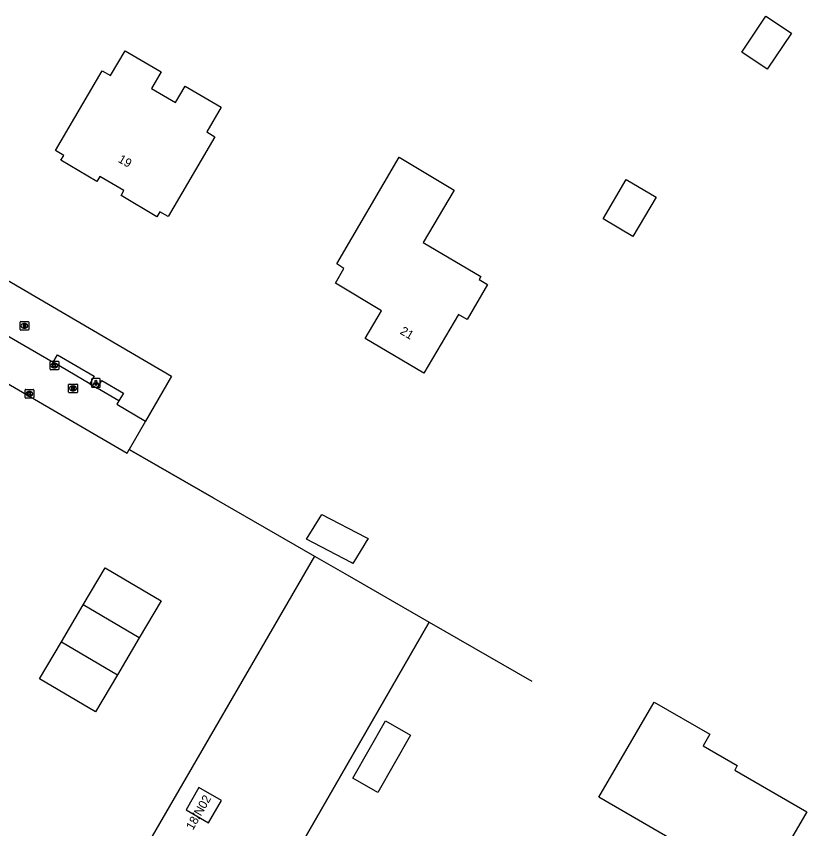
# Model space of a CAD drawing. Extents: x 156502 to 159074, y 384229 to 386094.
# Drawn here: x 157237.7 to 157328.7, y 385788.7 to 385882.2 of the extents above; entities that cross this region are included whole.
import ezdxf

# ---------------------------------------------------------------- set-up
doc = ezdxf.new("R2010")
doc.units = 0
for name, color, linetype in [('IMGEO_Gemengd_bos', 7, 'Continuous'), ('IMGEO_Grasland_overig', 7, 'Continuous'), ('IMGEO_Hek', 7, 'Continuous'), ('IMGEO_Kolk', 7, 'Continuous'), ('IMGEO_Lichtpunt', 7, 'Continuous'), ('IMGEO_Pand', 7, 'Continuous'), ('IMGEO_Pand_nummerreeks', 7, 'Continuous'), ('IMGEO_Pand_vergunning_verleend', 7, 'Continuous'), ('IMGEO_Rijbaan_lokaal_open', 7, 'Continuous'), ('IMGEO_Rioolput', 7, 'Continuous'), ('IMGEO_Voetpad_open', 7, 'Continuous')]:
    doc.layers.add(name, color=color, linetype=linetype)

msp = doc.modelspace()

# ---------------------------------------------------------------- linework, layer by layer
at = {"layer": 'IMGEO_Gemengd_bos'}
for points in [[(157272.043, 385820.045), (157246.925, 385776.791)], [(157272.043, 385820.045), (157275.516, 385818.046), (157285.222, 385812.462), (157254.627, 385759.261), (157295.91, 385735.365), (157303.574, 385730.965)]]:
    msp.add_lwpolyline(points, dxfattribs=at)
at = {"layer": 'IMGEO_Grasland_overig'}
msp.add_lwpolyline([(157250.702, 385832.309), (157260.436, 385826.723), (157272.043, 385820.045)], dxfattribs=at)
at = {"layer": 'IMGEO_Hek'}
for points in [[(157250.457, 385831.882), (157250.702, 385832.309)], [(157260.436, 385826.723), (157250.702, 385832.309)], [(157260.436, 385826.723), (157272.043, 385820.045)], [(157272.043, 385820.045), (157275.516, 385818.046)], [(157275.516, 385818.046), (157285.222, 385812.462)], [(157295.91, 385735.365), (157254.627, 385759.261), (157285.222, 385812.462)], [(157285.222, 385812.462), (157297.051, 385805.656)]]:
    msp.add_lwpolyline(points, dxfattribs=at)
at = {"layer": 'IMGEO_Kolk'}
for p, q in [((157241.584, 385841.563), (157241.584, 385842.415)), ((157241.659, 385842.489), (157242.511, 385842.489)), ((157242.095, 385841.709), (157242.07, 385841.709)), ((157242.072, 385842.269), (157242.097, 385842.269)), ((157242.585, 385842.415), (157242.585, 385841.563)), ((157242.511, 385841.489), (157241.659, 385841.489)), ((157238.706, 385838.307), (157238.706, 385839.159)), ((157238.781, 385839.233), (157239.633, 385839.233)), ((157239.194, 385839.013), (157239.219, 385839.013)), ((157239.707, 385839.159), (157239.707, 385838.307)), ((157239.633, 385838.233), (157238.781, 385838.233)), ((157239.217, 385838.453), (157239.192, 385838.453))]:
    msp.add_line(p, q, dxfattribs=at)
for points in [[(157241.584, 385841.563), (157241.584, 385842.415)], [(157241.659, 385842.489), (157242.511, 385842.489)], [(157241.905, 385842.189), (157242.028, 385842.189), (157242.028, 385842.038), (157242.158, 385842.189), (157242.322, 385842.189), (157242.176, 385842.038), (157242.329, 385841.789), (157242.177, 385841.789), (157242.092, 385841.953), (157242.028, 385841.886), (157242.028, 385841.789), (157241.905, 385841.789), (157241.905, 385842.189)], [(157242.585, 385842.415), (157242.585, 385841.563)], [(157242.511, 385841.489), (157241.659, 385841.489)], [(157238.706, 385838.307), (157238.706, 385839.159)], [(157238.781, 385839.233), (157239.633, 385839.233)], [(157239.027, 385838.933), (157239.15, 385838.933), (157239.15, 385838.782), (157239.28, 385838.933), (157239.444, 385838.933), (157239.298, 385838.782), (157239.451, 385838.533), (157239.299, 385838.533), (157239.214, 385838.697), (157239.15, 385838.63), (157239.15, 385838.533), (157239.027, 385838.533), (157239.027, 385838.933)], [(157239.707, 385839.159), (157239.707, 385838.307)], [(157239.633, 385838.233), (157238.781, 385838.233)]]:
    msp.add_lwpolyline(points, dxfattribs=at)
for centre, start, end in [((157241.661, 385842.413), 91.55205, 178.44795), ((157241.661, 385842.413), 91.55205, 178.44795), ((157242.509, 385842.413), 1.55205, 88.44795), ((157242.509, 385842.413), 1.55205, 88.44795), ((157241.661, 385841.565), 181.55205, 268.44795), ((157241.661, 385841.565), 181.55205, 268.44795), ((157242.509, 385841.565), 271.55205, 358.44795), ((157242.509, 385841.565), 271.55205, 358.44795), ((157238.783, 385839.157), 91.55205, 178.44795), ((157238.783, 385839.157), 91.55205, 178.44795), ((157239.631, 385839.157), 1.55205, 88.44795), ((157239.631, 385839.157), 1.55205, 88.44795), ((157238.783, 385838.309), 181.55205, 268.44795), ((157238.783, 385838.309), 181.55205, 268.44795), ((157239.631, 385838.309), 271.55205, 358.44795), ((157239.631, 385838.309), 271.55205, 358.44795)]:
    msp.add_arc(centre, 0.0765, start, end, dxfattribs=at)
for centre, major_axis, ratio, start_param, end_param in [((157242.071, 385841.989), (-0.387, 0.002), 0.722429, 4.712389, 7.853982), ((157242.096, 385841.989), (-0.39, 0.002), 0.717154, 1.570796, 4.712389), ((157239.193, 385838.733), (-0.387, 0.002), 0.722429, 4.712389, 7.853982), ((157239.218, 385838.733), (-0.39, 0.002), 0.717154, 1.570796, 4.712389)]:
    msp.add_ellipse(centre, major_axis=major_axis, ratio=ratio, start_param=start_param, end_param=end_param, dxfattribs=at)
at = {"layer": 'IMGEO_Lichtpunt'}
for p, q in [((157246.368, 385840.387), (157246.368, 385839.58)), ((157246.368, 385840.387), (157246.368, 385839.58)), ((157247.27, 385840.482), (157246.462, 385840.482)), ((157247.27, 385840.482), (157246.462, 385840.482)), ((157247.364, 385839.58), (157247.364, 385840.387)), ((157247.364, 385839.58), (157247.364, 385840.387)), ((157246.462, 385839.486), (157247.27, 385839.486)), ((157246.462, 385839.486), (157247.27, 385839.486))]:
    msp.add_line(p, q, dxfattribs=at)
for points in [[(157246.742, 385840.051), (157246.781, 385840.023), (157246.593, 385839.761), (157246.555, 385839.788), (157246.742, 385840.051)], [(157246.844, 385840.003), (157246.891, 385840.003), (157246.891, 385839.681), (157246.844, 385839.681), (157246.844, 385840.003)], [(157246.954, 385840.023), (157246.992, 385840.05), (157247.179, 385839.788), (157247.14, 385839.76), (157246.954, 385840.023)]]:
    msp.add_lwpolyline(points, dxfattribs=at)
msp.add_circle((157246.867, 385840.185), 0.0994, dxfattribs=at)
for centre, start, end in [((157246.462, 385840.387), 90, 180), ((157246.462, 385840.387), 90, 180), ((157247.27, 385840.387), 0, 90), ((157247.27, 385840.387), 0, 90), ((157246.462, 385839.58), 180, 270), ((157246.462, 385839.58), 180, 270), ((157247.27, 385839.58), 270, 0), ((157247.27, 385839.58), 270, 360)]:
    msp.add_arc(centre, 0.0946, start, end, dxfattribs=at)
at = {"layer": 'IMGEO_Pand'}
for points in [[(157321.246, 385878.052), (157324.014, 385882.185), (157326.945, 385880.221), (157324.176, 385876.089), (157321.246, 385878.052)], [(157242.826, 385865.609), (157243.156, 385866.162), (157242.212, 385866.726), (157247.585, 385875.898), (157248.555, 385875.375), (157250.234, 385878.2), (157254.372, 385875.786), (157253.258, 385873.877), (157256.043, 385872.253), (157257.148, 385874.146), (157261.288, 385871.729), (157259.62, 385868.87), (157260.57, 385868.316), (157255.182, 385859.122), (157254.232, 385859.683), (157253.898, 385859.114), (157249.757, 385861.548), (157250.086, 385862.113), (157247.316, 385863.723), (157246.981, 385863.155), (157242.826, 385865.609)], [(157281.782, 385865.949), (157288.102, 385862.187), (157284.558, 385856.153), (157291.197, 385852.247), (157290.981, 385851.88), (157291.963, 385851.3), (157289.6, 385847.295), (157288.628, 385847.855), (157284.619, 385841.103), (157277.855, 385845.082), (157279.744, 385848.293), (157274.438, 385851.45), (157275.432, 385853.153), (157274.591, 385853.675), (157281.782, 385865.949)], [(157307.932, 385863.396), (157311.381, 385861.357), (157308.708, 385856.835), (157305.259, 385858.875), (157307.932, 385863.396)], [(157277.909, 385822.228), (157278.209, 385822.071), (157278.002, 385821.731), (157277.726, 385821.278), (157276.462, 385819.199), (157276.241, 385819.314), (157271.119, 385821.984), (157272.866, 385824.855), (157277.909, 385822.228)], [(157317.548, 385799.558), (157316.776, 385798.21), (157320.718, 385795.937), (157320.434, 385795.406), (157328.719, 385790.614), (157326.966, 385787.584), (157327.534, 385787.243), (157326.922, 385786.2), (157328.262, 385785.426), (157325.36, 385780.382), (157319.65, 385783.69), (157315.58, 385786.049), (157304.76, 385792.318), (157311.146, 385803.25), (157317.548, 385799.558)], [(157280.225, 385801.102), (157283.103, 385799.455), (157279.316, 385792.837), (157276.438, 385794.484), (157280.225, 385801.102)], [(157259.842, 385789.359), (157261.318, 385791.939), (157258.721, 385793.426), (157257.251, 385790.839), (157259.842, 385789.359)]]:
    msp.add_lwpolyline(points, dxfattribs=at)
at = {"layer": 'IMGEO_Pand_vergunning_verleend'}
for points in [[(157245.411, 385814.459), (157247.925, 385818.722), (157254.374, 385814.918), (157251.859, 385810.655)], [(157242.896, 385810.197), (157245.411, 385814.459)], [(157251.859, 385810.655), (157245.411, 385814.459)], [(157249.345, 385806.393), (157246.83, 385802.13), (157240.381, 385805.934), (157242.896, 385810.197)], [(157242.896, 385810.197), (157249.345, 385806.393)], [(157251.859, 385810.655), (157249.345, 385806.393)]]:
    msp.add_lwpolyline(points, dxfattribs=at)
at = {"layer": 'IMGEO_Rijbaan_lokaal_open'}
for points in [[(157205.703, 385857.935), (157250.457, 385831.882), (157250.702, 385832.309)], [(157235.934, 385845.88), (157241.947, 385842.373)], [(157246.178, 385839.897), (157241.947, 385842.373)], [(157246.178, 385839.897), (157247.026, 385839.395)], [(157249.511, 385837.937), (157247.026, 385839.395)], [(157249.511, 385837.937), (157249.263, 385837.527), (157252.582, 385835.588)], [(157252.582, 385835.588), (157250.702, 385832.309)]]:
    msp.add_lwpolyline(points, dxfattribs=at)
at = {"layer": 'IMGEO_Rioolput'}
for p, q in [((157238.138, 385846.129), (157238.138, 385846.981)), ((157238.213, 385847.055), (157239.065, 385847.055)), ((157238.626, 385846.835), (157238.651, 385846.835)), ((157239.139, 385846.981), (157239.139, 385846.129)), ((157239.065, 385846.055), (157238.213, 385846.055)), ((157238.649, 385846.275), (157238.624, 385846.275)), ((157243.728, 385838.934), (157243.728, 385839.786)), ((157243.803, 385839.86), (157244.655, 385839.86)), ((157244.729, 385839.786), (157244.729, 385838.934)), ((157244.655, 385838.86), (157243.803, 385838.86)), ((157244.239, 385839.08), (157244.214, 385839.08)), ((157244.216, 385839.64), (157244.241, 385839.64))]:
    msp.add_line(p, q, dxfattribs=at)
for points in [[(157238.138, 385846.129), (157238.138, 385846.981)], [(157238.213, 385847.055), (157239.065, 385847.055)], [(157238.727, 385846.753), (157238.475, 385846.755), (157238.475, 385846.355)], [(157238.475, 385846.355), (157238.599, 385846.355), (157238.599, 385846.517), (157238.61, 385846.517)], [(157238.653, 385846.674), (157238.599, 385846.674), (157238.599, 385846.593)], [(157238.599, 385846.593), (157238.651, 385846.593)], [(157238.657, 385846.488), (157238.728, 385846.355), (157238.868, 385846.355), (157238.803, 385846.481)], [(157239.139, 385846.981), (157239.139, 385846.129)], [(157239.065, 385846.055), (157238.213, 385846.055)], [(157243.728, 385838.934), (157243.728, 385839.786)], [(157243.803, 385839.86), (157244.655, 385839.86)], [(157244.729, 385839.786), (157244.729, 385838.934)], [(157244.655, 385838.86), (157243.803, 385838.86)], [(157244.317, 385839.558), (157244.065, 385839.56), (157244.065, 385839.16)], [(157244.065, 385839.16), (157244.189, 385839.16), (157244.189, 385839.322), (157244.2, 385839.322)], [(157244.243, 385839.479), (157244.189, 385839.479), (157244.189, 385839.398)], [(157244.189, 385839.398), (157244.241, 385839.398)], [(157244.247, 385839.293), (157244.318, 385839.16), (157244.458, 385839.16), (157244.393, 385839.286)]]:
    msp.add_lwpolyline(points, dxfattribs=at)
for centre, radius, start, end in [((157238.215, 385846.979), 0.0765, 91.55205, 178.44795), ((157238.215, 385846.979), 0.0765, 91.55205, 178.44795), ((157238.609, 385846.464), 0.0533, 26.02933, 88.69889), ((157238.635, 385846.782), 0.19, 274.7715, 282.96867), ((157238.659, 385846.578), 0.0964, 77.00612, 93.18647), ((157238.673, 385846.635), 0.0378, 276.66336, 79.67722), ((157238.726, 385846.643), 0.109, 350.36119, 89.41601), ((157238.724, 385846.643), 0.112, 277.58423, 350.98172), ((157238.708, 385846.428), 0.108, 29.51342, 73.79051), ((157239.063, 385846.979), 0.0765, 1.55205, 88.44795), ((157239.063, 385846.979), 0.0765, 1.55205, 88.44795), ((157238.215, 385846.131), 0.0765, 181.55205, 268.44795), ((157238.215, 385846.131), 0.0765, 181.55205, 268.44795), ((157239.063, 385846.131), 0.0765, 271.55205, 358.44795), ((157239.063, 385846.131), 0.0765, 271.55205, 358.44795), ((157243.805, 385839.784), 0.0765, 91.55205, 178.44795), ((157243.805, 385839.784), 0.0765, 91.55205, 178.44795), ((157244.653, 385839.784), 0.0765, 1.55205, 88.44795), ((157244.653, 385839.784), 0.0765, 1.55205, 88.44795), ((157243.805, 385838.936), 0.0765, 181.55205, 268.44795), ((157243.805, 385838.936), 0.0765, 181.55205, 268.44795), ((157244.199, 385839.269), 0.0533, 26.02933, 88.69889), ((157244.225, 385839.587), 0.19, 274.7715, 282.96867), ((157244.249, 385839.383), 0.0964, 77.00612, 93.18647), ((157244.263, 385839.44), 0.0378, 276.66336, 79.67722), ((157244.316, 385839.448), 0.109, 350.36119, 89.41601), ((157244.314, 385839.448), 0.112, 277.58423, 350.98172), ((157244.298, 385839.233), 0.108, 29.51342, 73.79051), ((157244.653, 385838.936), 0.0765, 271.55205, 358.44795), ((157244.653, 385838.936), 0.0765, 271.55205, 358.44795)]:
    msp.add_arc(centre, radius, start, end, dxfattribs=at)
for centre, major_axis, ratio, start_param, end_param in [((157238.625, 385846.555), (-0.387, 0.002), 0.722429, 4.712389, 7.853982), ((157238.65, 385846.555), (-0.39, 0.002), 0.717154, 1.570796, 4.712389), ((157244.215, 385839.36), (-0.387, 0.002), 0.722429, 4.712389, 7.853982), ((157244.24, 385839.36), (-0.39, 0.002), 0.717154, 1.570796, 4.712389)]:
    msp.add_ellipse(centre, major_axis=major_axis, ratio=ratio, start_param=start_param, end_param=end_param, dxfattribs=at)
at = {"layer": 'IMGEO_Voetpad_open'}
for points in [[(157218.954, 385862.085), (157226.078, 385857.975), (157255.558, 385840.78), (157252.582, 385835.588)], [(157241.947, 385842.373), (157242.451, 385843.218), (157246.682, 385840.755), (157246.178, 385839.897)], [(157247.026, 385839.395), (157247.532, 385840.247), (157250.029, 385838.788), (157249.511, 385837.937)]]:
    msp.add_lwpolyline(points, dxfattribs=at)

# ---------------------------------------------------------------- texts
at = {"layer": 'IMGEO_Pand_nummerreeks'}
for s, rotation, p in [('19', 329.82783, (157249.332, 385865.466)), ('21', 329.32753, (157281.803, 385845.688)), ('18/N02', 60.16009, (157258.033, 385788.444))]:
    msp.add_text(s, height=1, rotation=rotation, dxfattribs=at).set_placement(p)

doc.saveas('drawing.dxf')
